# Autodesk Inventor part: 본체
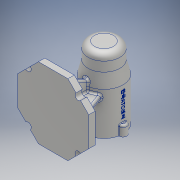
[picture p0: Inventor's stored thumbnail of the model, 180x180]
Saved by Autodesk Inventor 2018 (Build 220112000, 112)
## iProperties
Created: 2019-12
Part Number: 본체
Material: 알루미늄 6061
Document SubType Name: Modeling
Designer: Administrator
Density: 2.7 g/cm^3
Appearance: 알루미늄 - 평지
Mass: 725.987 g
Surface Area: 715.463 cm^2
Volume: 268.884 cm^3
Author: Administrator
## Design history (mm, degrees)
sketch "스케치1"
  geometry: L1 (23.196, -56)-(-23.196, -56); L2 (-56, -23.196)-(-56, 23.196); L3 (-23.196, 56)-(23.196, 56); L4 (56, 23.196)-(56, -23.196); L5 (23.196, 56)-(36.062, 43.134); L6 (43.134, 36.062)-(56, 23.196); L7 (56, -23.196)-(43.134, -36.062); L8 (36.062, -43.134)-(23.196, -56); L9 (-56, 23.196)-(-43.134, 36.062); L10 (-36.062, 43.134)-(-23.196, 56); L11 (-23.196, -56)-(-36.062, -43.134); L12 (-43.134, -36.062)-(-56, -23.196); A1 r 5 centre (39.598, 39.598) between (36.062, 43.134) and (43.134, 36.062); A2 r 5 centre (39.598, -39.598) between (43.134, -36.062) and (36.062, -43.134); A3 r 5 centre (-39.598, 39.598) between (-43.134, 36.062) and (-36.062, 43.134); A4 r 5 centre (-39.598, -39.598) between (-36.062, -43.134) and (-43.134, -36.062); 1 further point
  constraints: 24 end point, 8 point on circle, 4 centre point, 1 midpoint
  dimensions: "d1" = 10 diameter of A1; "d2" = 10 diameter of A2; "d3" = 10 diameter of A3; "d4" = 10 diameter of A4
extrude "돌출1" new body sketch "스케치1" distance "d5" = 10; taper "d6" = 0 deg
sketch "스케치2"
  geometry: L1 (-56, 23.196)-(-56, -23.196) reference; L2 (56, -23.196)-(56, 23.196) reference; L3 (23.196, -56)-(-23.196, -56); L4 (4, 31)-(-4, 31); L5 (-23.196, 56)-(23.196, 56); L6 (4, -38)-(-4, -38); L7 (-36, 4)-(-36, -4); L8 (36, -4)-(36, 4); L9 (-4, -38)-(-4, -4); L10 (-4, 4)-(-4, 31); L11 (4, -38)-(4, -4); L12 (4, 4)-(4, 31); L13 (-36, -4)-(-4, -4); L14 (4, -4)-(36, -4); L15 (-36, 4)-(-4, 4); L16 (4, 4)-(36, 4); 1 other entity
  constraints: 28 end point, 4 parallel, 2 horizontal, 1 other
  dimensions: "d12" = 25 dimension on L4; "d13" = 18 distance between parallel lines of L3 L6; "d14" = 20 distance between parallel lines of L1 L7; "d15" = 20 distance between parallel lines of L2 L8
extrude "돌출2" join sketch "스케치2" distance "d16" = 70; taper "d17" = 0 deg
sketch "스케치3"
  geometry: L1 (-18, 0)-(-5.134, 0) reference; L2 (0, 0)-(32.642, 70); L3 (0, 0)-(0, 70); L4 (34, 70)-(0, 70) reference; L5 (0, 70)-(32.642, 70); 1 further point
  constraints: 6 end point, 2 point on line, 1 vertical
  dimensions: "d19" = 115 deg angle of L1 L2
extrude "돌출3" cut sketch "스케치3" extent not by distance; stored distance "d20" = 70; taper "d21" = 0 deg
sketch "스케치4"
  geometry: L1 (0, 0)-(32, 0) reference; L2 (0, 0)-(25.478, 70); L3 (72, 0)-(40, 0) reference; L4 (72, 0)-(46.522, 70); L5 (79.134, 0)-(92, 0) reference; L6 (-20, 0)-(-7.134, 0) reference; L7 (0, 70)-(32, 70) reference; L8 (0, 0)-(0, 70); L9 (0, 70)-(25.478, 70); L10 (72, 70)-(40, 70) reference; L11 (72, 0)-(72, 70); L12 (72, 70)-(46.522, 70); 1 further point
  constraints: 12 end point, 2 point on line, 2 vertical
  dimensions: "d22" = 110 deg angle of L5 L4; "d23" = 110 deg angle of L6 L2
extrude "돌출4" cut sketch "스케치4" extent not by distance; stored distance "d24" = 70; taper "d25" = 0 deg
node "작업 평면1"
sketch "스케치5"
  geometry: L1 (60, 0)-(47.134, 0) reference; L2 (60, 70)-(60, 100); L3 (-52, -10)-(-52, 0) reference; L4 (60, 70)-(-52, 70); L5 (-52, 70)-(-52, 95); L6 (-52, 95)-(-27, 95); L7 (-27, 95)-(-7, 100); L8 (-7, 100)-(60, 100); 1 further point
  constraints: 12 end point, 3 perpendicular, 1 horizontal
  dimensions: "d26" = 70 distance of L1.start L2.start; "d27" = 30 distance of L2.start L2.end; "d29" = 25 distance of L4.end L5.end; "d30" = 25 distance of L5.end L6.end
revolve "회전1" sketch "스케치5" stored, may be unused: angle "d32" = 90 deg
sketch "스케치6"
  geometry: C1 r 21 at (0, 0); 1 further point
  constraints: 1 centre point
  dimensions: "d33" = 42 diameter of C1
extrude "돌출5" cut sketch "스케치6" distance "d34" = 15; taper "d35" = 0 deg
sketch "스케치7"
  geometry: C1 r 24 at (0, 0); 1 further point
  constraints: 1 centre point
  dimensions: "d36" = 48 diameter of C1
extrude "돌출6" cut sketch "스케치7" distance "d37" = 54; taper "d38" = 0 deg
sketch "스케치8"
  geometry: C1 r 21 at (0, 0); 1 further point
  constraints: 1 centre point
  dimensions: "d39" = 42 diameter of C1
extrude "돌출7" cut sketch "스케치8" distance "d40" = 12; taper "d41" = 0 deg
sketch "스케치9"
  geometry: C1 r 17.5 at (0, 0); 1 further point
  constraints: 1 centre point
  dimensions: "d42" = 35 diameter of C1
extrude "돌출8" cut sketch "스케치9" distance "d43" = 18; taper "d44" = 0 deg
sketch "스케치10"
  geometry: C1 r 16 at (0, 0); 1 further point
  constraints: 1 centre point
  dimensions: "d45" = 32 diameter of C1
extrude "돌출9" cut sketch "스케치10" distance "d46" = 4; taper "d47" = 0 deg
sketch "스케치11"
  geometry: C1 r 10.5 at (0, 0); 1 further point
  constraints: 1 centre point
  dimensions: "d48" = 21 diameter of C1
extrude "돌출10" cut sketch "스케치11" distance "d49" = 3; taper "d50" = 0 deg
fillet "모깎기1" dims "d51" = 10
fillet "모깎기2" dims "d52" = 3
fillet "모깎기3" dims "d53" = 0.3
fillet "모깎기4" dims "d54" = 3
sketch "스케치12"
  geometry: C1 r 6 at (0, 30); C2 r 6 at (30, 0); C3 r 6 at (-30, 0); C4 r 6 at (0, -30); A1 r 30 centre (0, 0) between (4, -29.732) and (-4, -29.732) reference; A2 r 30 centre (0, 0) between (4, -29.732) and (-4, -29.732) reference; 1 further point
  constraints: 4 centre point, 4 point on circle
  dimensions: "d55" = 12 diameter of C1; "d56" = 12 diameter of C2; "d57" = 12 diameter of C3; "d58" = 12 diameter of C4
extrude "돌출11" join sketch "스케치12" distance "d59" = 16; taper "d60" = 0 deg
fillet "모깎기5" dims "d61" = 3, "d62" = 1
sketch "스케치13"
  geometry: C1 r 7.5 at (0, -30) reference; A1 r 30 centre (0, -30) between (4, -59.732) and (-4, -59.732); A2 r 30 centre (0, -30) between (4, -59.732) and (-4, -59.732) reference; 5 further points
  constraints: 4 point on circle, 1 centre point, 1 coincident
  dimensions: "d63" = 60 diameter of A1
hole "구멍1" sketch "스케치13" at (0, 0), (30, -30), (0, -60), (-30, -30) diameter "d64" = 3.242; stored, may be unused: countersink angle "d68" = 90 deg, drill point angle "d70" = 118 deg; dims "d65" = 8, "d66" = 4, "d67" = 2, "d69" = 11
fillet "모깎기6" dims "d71" = 3
node "작업 평면2"
sketch "스케치14"
  geometry: L1 (21, -33.5)-(-21, -33.5) reference; L2 (0, -33.5)-(0, 92.162); L3 (21, 7.5)-(-21, 7.5); 3 further points
  constraints: 4 end point, 2 midpoint, 1 parallel, 1 vertical, 1 other
  dimensions: "d72" = 41 distance between parallel lines of L1 L3
feature "엠보싱1" sketch "스케치14" dims "d1" = 10, "d2" = 10, "d3" = 10, "d4" = 10, "d12" = 25, "d13" = 18, "d14" = 20, "d15" = 20, "d73" = 0.5, "d74" = 0
node "솔리드1"
